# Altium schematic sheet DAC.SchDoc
size A3
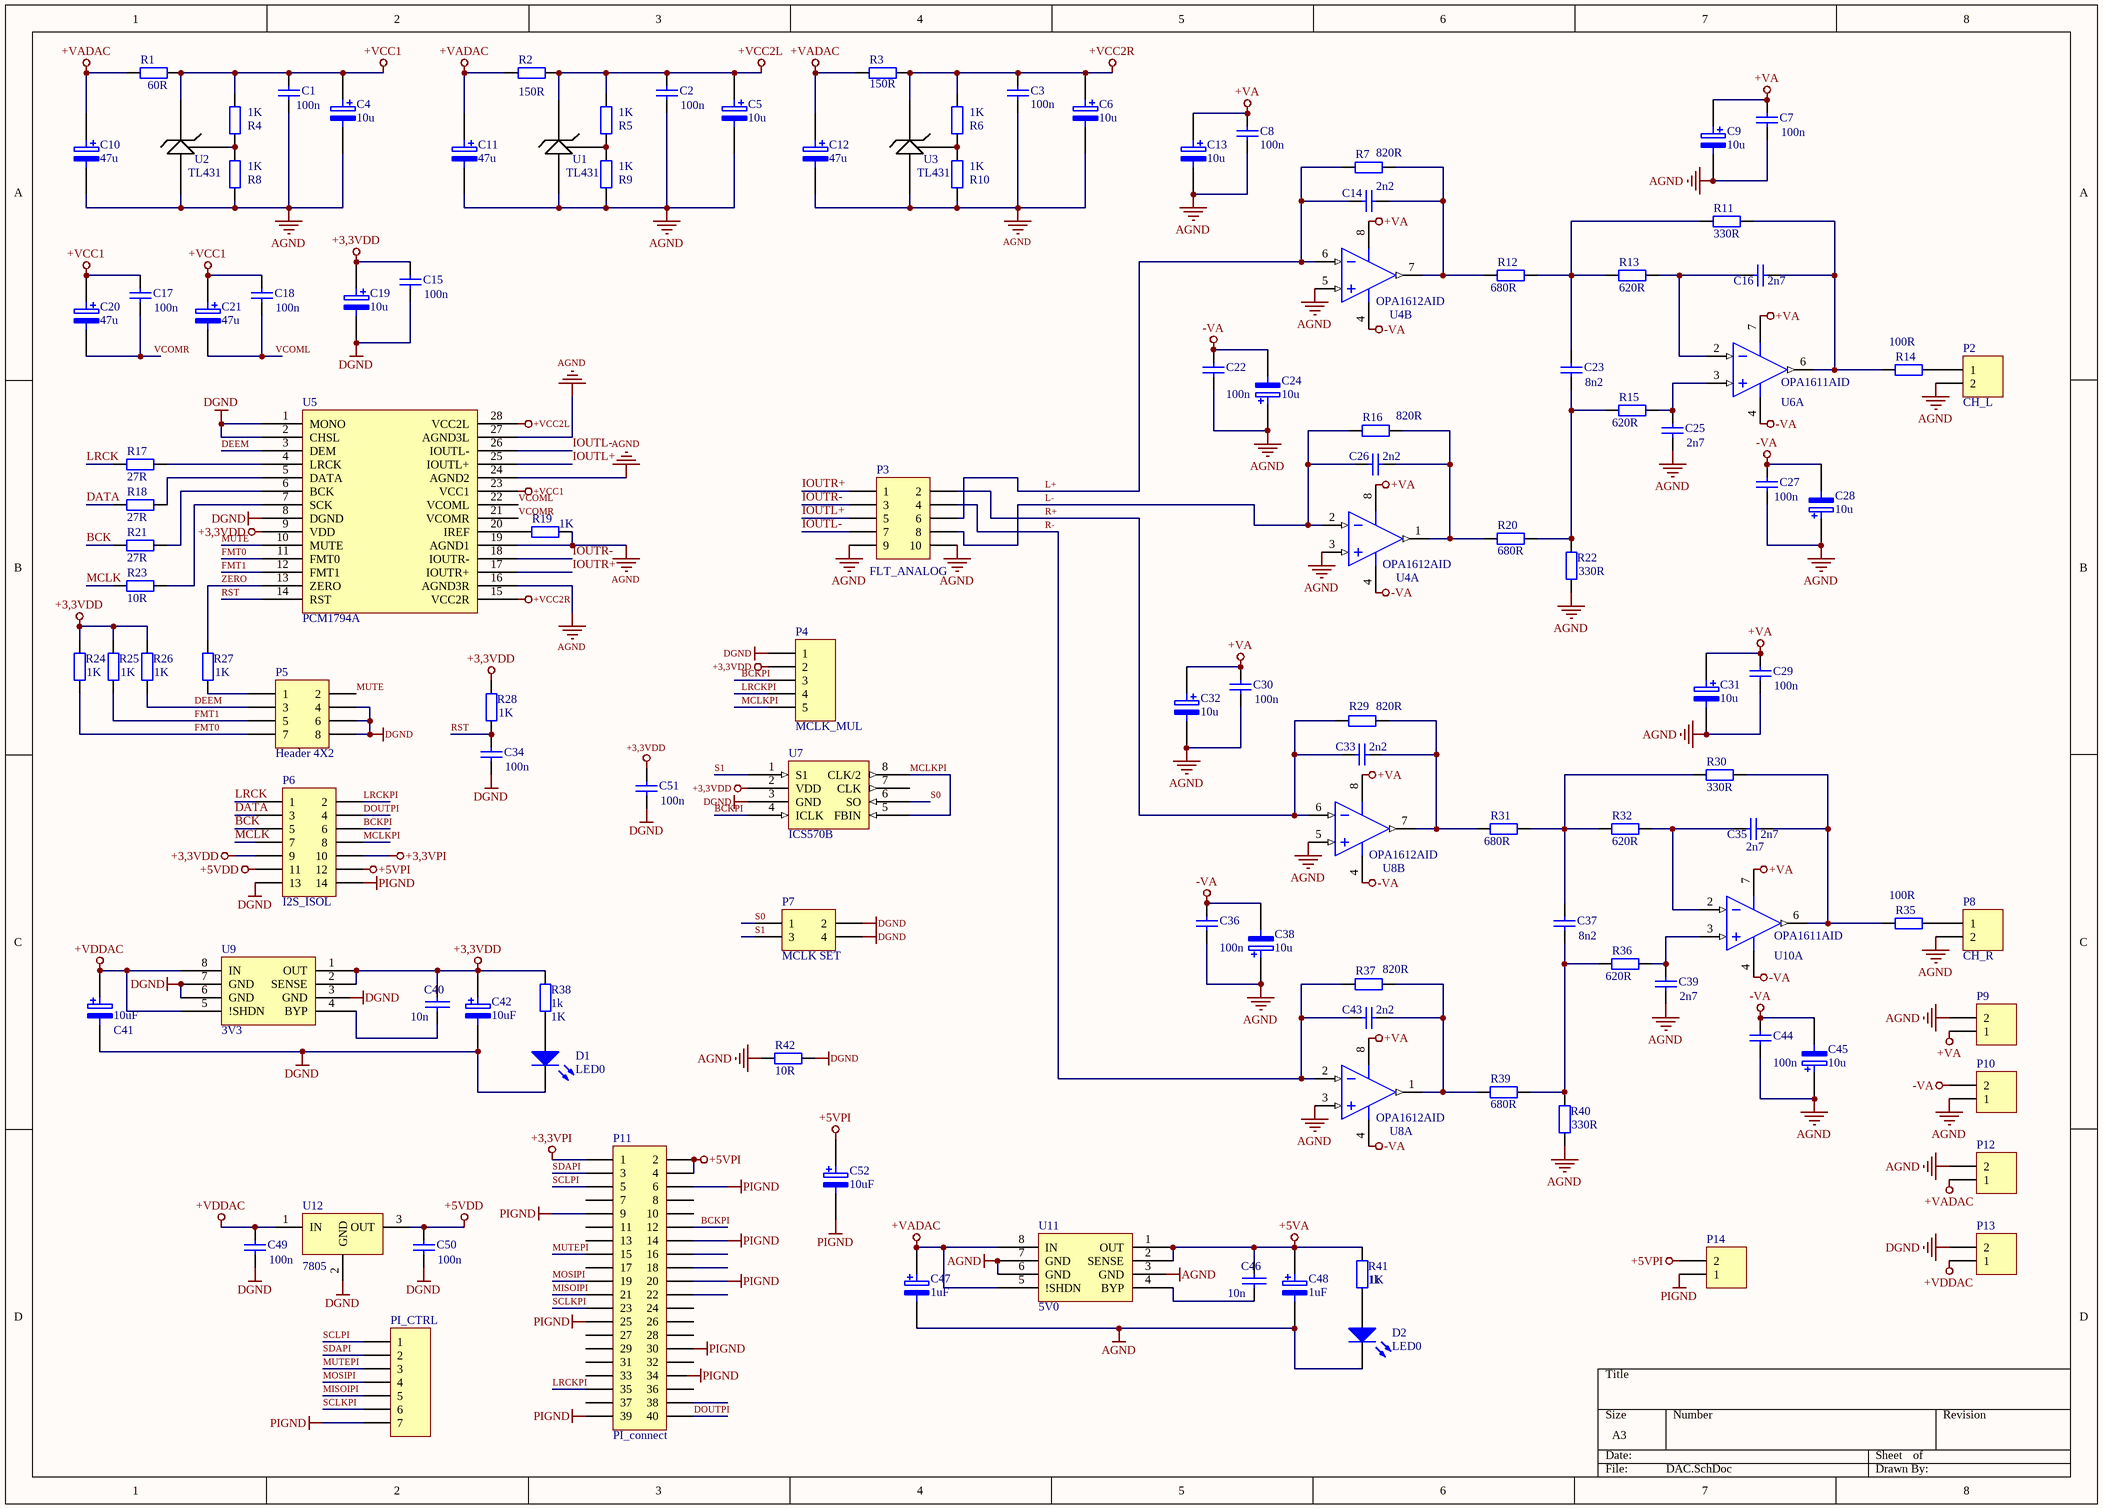
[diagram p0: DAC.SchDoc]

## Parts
C1  value 100n  [1206]
C2  100n  [1206]
C3  100n  [1206]
C4  10u  [10uf/25v]
C5  10u  [10uf/25v]
C6  10u  [10uf/25v]
C7  100n  [1206]
C8  100n  [1206]
C9  10u  [10uf/25v]
C10  47u  [47u/25v]
C11  47u  [47u/25v]
C12  47u  [47u/25v]
C13  10u  [10uf/25v]
C14  2n2  [RAD0.2]
C15  value 100n  [1206]
C16  2n7  [RAD0.2]
C17  value 100n  [1206]
C18  value 100n  [1206]
C19  value 10u  [10uf/25v]
C20  47u  [47u/25v]
C21  47u  [47u/25v]
C22  100n  [1206]
C23  8n2  [RAD0.2]
C24  10u  [10uf/25v]
C25  2n7  [RAD0.2]
C26  2n2  [RAD0.2]
C27  100n  [1206]
C28  10u  [10uf/25v]
C29  100n  [1206]
C30  100n  [1206]
C31  10u  [10uf/25v]
C32  10u  [10uf/25v]
C33  2n2  [RAD0.2]
C34  100n  [1206]
C35  2n7  [RAD0.2]
C36  100n  [1206]
C37  8n2  [RAD0.2]
C38  10u  [10uf/25v]
C39  2n7  [RAD0.2]
C40  10n  [1206]
C41  10uF  [10uSMD]
C42  10uF  [3528]
C43  2n2  [RAD0.2]
C44  100n  [1206]
C45  10u  [10uf/25v]
C46  10n  [1206]
C47  1uF  [10uSMD]
C48  1uF  [3528]
C49  value 100n  [1206]
C50  value 100n  [1206]
C51  100n  [1206]
C52  10uF  [3528]
D1  LED0  [1206]
D2  LED0  [1206]
P2  CH_L  [HDR1X2]
P3  FLT_ANALOG  [HDR2X5]
P4  MCLK_MUL  [HDR1X5]
P5  Header 4X2  [HDR2X4]
P6  I2S_ISOL  [HDR2X7]
P7  MCLK SET  [HDR2X2]
P8  CH_R  [HDR1X2]
P9  (no value)  [wago]
P10  (no value)  [wago]
P11  PI_connect  [HDR2X20]
P12  (no value)  [wago]
P13  (no value)  [wago]
P14  (no value)  [wago]
PI_CTRL  (no value)  [HDR1X7]
R1  60R  [1206]
R2  150R  [1206]
R3  150R  [1206]
R4  1k  [1206]
R5  1k  [1206]
R6  1k  [1206]
R7  820R  [1206]
R8  1k  [1206]
R9  1k  [1206]
R10  1k  [1206]
R11  330R  [1206]
R12  680R  [1206]
R13  620R  [1206]
R14  100R  [1206]
R15  620R  [1206]
R16  820R  [1206]
R17  27R  [1206]
R18  27R  [1206]
R19  1k  [1206]
R20  680R  [1206]
R21  27R  [1206]
R22  330R  [1206]
R23  value 10R  [1206]  (hidden comment: 27R)
R24  1k  [1206]
R25  1k  [1206]
R26  1k  [1206]
R27  1k  [1206]
R28  1k  [1206]
R29  820R  [1206]
R30  330R  [1206]
R31  680R  [1206]
R32  620R  [1206]
R35  100R  [1206]
R36  620R  [1206]
R37  820R  [1206]
R38  1k  [1206]
R39  680R  [1206]
R40  330R  [1206]
R41  1k  [1206]
R42  10R  [1206]
U1  TL431  [sot23-3]
U2  TL431  [sot23-3]
U3  TL431  [sot23-3]
U4  OPA1612AID  [TI-D8_N]  (parts A,B of 2)
U5  PCM1794A  [pcm1796]
U6  OPA1611AID  [TI-D8_N]  (part A of 2)
U7  ICS570B  [TI-D8_n]
U8  OPA1612AID  [TI-D8_N]  (parts A,B of 2)
U9  3V3  [TI-D8_N]
U10  OPA1611AID  [TI-D8_N]  (part A of 2)
U11  5V0  [TI-D8_n]
U12  7805  [78XXST]

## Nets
+3,3VDD: C15.1 C19.1 C40.1 C42.1 C51.1 P4.2 P6.9 R24.1 R25.1 R26.1 R28.1 R38.1 U5.9(VDD) U7.2(VDD) U9.1(OUT) U9.2(SENSE)
+3,3VPI: P6.10 P11.1
+5VA: C46.1 C48.1 R41.1 U11.1(OUT) U11.2(SENSE)
+5VDD: C50.1 P6.11 U12.3(OUT)
+5VPI: C52.1 P6.12 P11.2 P11.4 P14.2
+VA: C7.1 C8.1 C9.1 C13.1 C29.1 C30.1 C31.1 C32.1 P9.1 U4.8(V+) U6.7(V+) U8.8(V+) U10.7(V+)
+VADAC: C10.1 C11.1 C12.1 C47.1 P12.1 R1.1 R2.1 R3.1 U11.5(!SHDN) U11.8(IN)
+VCC1: C1.1 C4.1 C17.1 C18.1 C20.1 C21.1 R1.2 R4.1 U2.1(K) U5.23(VCC1)
+VCC2L: C2.1 C5.1 R2.2 R5.1 U1.1(K) U5.28(VCC2L)
+VCC2R: C3.1 C6.1 R3.2 R6.1 U3.1(K) U5.15(VCC2R)
+VDDAC: C41.1 C49.1 P13.1 U9.5(!SHDN) U9.8(IN) U12.1(IN)
-VA: C22.1 C24.2 C27.1 C28.2 C36.1 C38.2 C44.1 C45.2 P10.2 U4.4(V-) U6.4(V-) U8.4(V-) U10.4(V-)
AGND: C1.2 C2.2 C3.2 C4.2 C5.2 C6.2 C7.2 C8.2 C9.2 C10.2 C11.2 C12.2 C13.2 C22.2 C24.1 C25.2 C27.2 C28.1 C29.2 C30.2 C31.2 C32.2 C36.2 C38.1 C39.2 C44.2 C45.1 C47.2 C48.2 D2.2(K) P2.2 P3.9 P3.10 P8.2 P9.2 P10.1 P12.2 R8.2 R9.2 R10.2 R19.1 R22.1 R40.1 R42.1 U1.3(A) U2.3(A) U3.3(A) U4.3(IN_A+) U4.5(IN_B+) U5.16(AGND3R) U5.19(AGND1) U5.24(AGND2) U5.27(AGND3L) U8.3(IN_A+) U8.5(IN_B+) U11.6(GND) U11.7(GND)
DGND: C15.2 C19.2 C34.2 C41.2 C42.2 C49.2 C50.2 C51.2 D1.2(K) P4.1 P5.4 P5.6 P5.8 P6.13 P7.2 P7.4 P13.2 R42.2 U5.1(MONO) U5.2(CHSL) U5.8(DGND) U7.3(GND) U9.6(GND) U9.7(GND) U12.2(GND)
PIGND: C52.2 P6.14 P11.6 P11.9 P11.14 P11.20 P11.25 P11.30 P11.39 P14.1 PI_CTRL.7
BCK: P6.5 R21.1
BCKPI: P4.3 P6.6 P11.12 U7.4(ICLK)
DATA: P6.3 R18.1
DEEM: P5.3 R26.2 U5.3(DEM)
DOUTPI: P6.4 P11.40
FMT0: P5.7 R24.2 U5.11(FMT0)
FMT1: P5.5 R25.2 U5.12(FMT1)
IOUTL+: P3.5 U5.25(IOUTL+)
IOUTL-: P3.7 U5.26(IOUTL-)
IOUTR+: P3.1 U5.17(IOUTR+)
IOUTR-: P3.3 U5.18(IOUTR-)
L+: C14.1 P3.6 R7.2 U4.6(IN_B-)
L-: C26.1 P3.8 R16.2 U4.2(IN_A-)
LRCK: P6.1 R17.1
LRCKPI: P4.4 P6.2 P11.35
MCLK: P6.7 R23.1
MCLKPI: P4.5 P6.8 U7.5(FBIN) U7.8(CLK/2)
MISOIPI: P11.21 PI_CTRL.5
MOSIPI: P11.19 PI_CTRL.4
MUTE: P5.2 U5.10(MUTE)
MUTEPI: P11.15 PI_CTRL.3
R+: C33.1 P3.2 R29.2 U8.6(IN_B-)
R-: C43.1 P3.4 R37.2 U8.2(IN_A-)
RST: C34.1 R28.2 U5.14(RST)
S0: P7.1 U7.6(SO)
S1: P7.3 U7.1(S1)
SCLKPI: P11.23 PI_CTRL.6
SCLPI: P11.5 PI_CTRL.1
SDAPI: P11.3 PI_CTRL.2
VCOML: C18.2 C21.2 U5.22(VCOML)
VCOMR: C17.2 C20.2 U5.21(VCOMR)
ZERO: R27.1 U5.13(ZERO)
NetC14_2: C14.2 R7.1 R12.2 U4.7(OUT_B)
NetC16_1: C16.1 R13.1 U6.2(IN-)
NetC16_2: C16.2 R11.1 R14.2 U6.6(OUT)
NetC23_1: C23.1 R11.2 R12.1 R13.2
NetC23_2: C23.2 R15.2 R20.1 R22.2
NetC25_1: C25.1 R15.1 U6.3(IN+)
NetC26_2: C26.2 R16.1 R20.2 U4.1(OUT_A)
NetC33_2: C33.2 R29.1 R31.2 U8.7(OUT_B)
NetC35_1: C35.1 R32.1 U10.2(IN-)
NetC35_2: C35.2 R30.1 R35.2 U10.6(OUT)
NetC37_1: C37.1 R30.2 R31.1 R32.2
NetC37_2: C37.2 R36.2 R39.1 R40.2
NetC39_1: C39.1 R36.1 U10.3(IN+)
NetC40_2: C40.2 U9.4(BYP)
NetC43_2: C43.2 R37.1 R39.2 U8.1(OUT_A)
NetC46_2: C46.2 U11.4(BYP)
NetD1_1: D1.1(A) R38.2
NetD2_1: D2.1(A) R41.2
NetP2_1: P2.1 R14.1
NetP5_1: P5.1 R27.2
NetP8_1: P8.1 R35.1
NetR4_2: R4.2 R8.1 U2.2(REF)
NetR5_2: R5.2 R9.1 U1.2(REF)
NetR6_2: R6.2 R10.1 U3.2(REF)
NetR17_2: R17.2 U5.4(LRCK)
NetR18_2: R18.2 U5.5(DATA)
NetR19_2: R19.2 U5.20(IREF)
NetR21_2: R21.2 U5.6(BCK)
NetR23_2: R23.2 U5.7(SCK)

Not connected (* = marked no-connect by the designer): P11 7 8 10 11 13 16 17 18 22 24 26 27 28 29 31 32 33 34 36 37 38; U7 7(CLK); U9 3(GND); U11 3(GND)

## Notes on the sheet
- Labels drawn without touching a wire or pin: AGND, DGND, PIGND

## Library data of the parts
C1-C3 C7 C8 C14-C18 C22 C23 C25-C27 C29 C30 C33-C37 C39 C43 C44 C49-C51 = Cap: Capacitor
C4-C6 C9-C13 C19-C21 C24 C28 C31 C32 C38 C41 C42 C45 C47 C48 C52 = ELECTRO2: Electrolytic Capacitor
C40 C46 = CAP: Capacitor
D1 D2 = LED0: Typical INFRARED GaAs LED
P2 P8-P10 P12-P14 = Header 2: Header, 2-Pin
P3 = Header 5X2: Header, 5-Pin, Dual row
P4 = Header 5: Header, 5-Pin
P5 = Header 4X2: Header, 4-Pin, Dual row
P6 = Header 7X2: Header, 7-Pin, Dual row
P7 = Header 2X2: Header, 2-Pin, Dual row
P11 = Header 20X2: Header, 20-Pin, Dual row
PI_CTRL = Header 7: Header, 7-Pin
R1-R32 R35-R42 = Res2: Resistor
U4 U8 = OPA1612AID: 1.1 nV/rtHz Noise, Low Power, Precision Operational Amplifier, 4.5 to 36 V, -40 to 85 degC, 8-pin SOIC (D8), Green (RoHS & no Sb/Br); Manufacturer: Texas Instruments; GBW(Typ)(MHz): 40; Iq per channel(Max)(mA): 4.5; Number of Channels: 2; SubFamily: Audio Operational Amplifier; Vmax(V): 36; Vn at Flatband(Typ)(nV/rtHz): 1.1
U6 U10 = OPA1611AID: 1.1 nV/rtHz Noise, Low Power, Precision Operational Amplifier, 4.5 to 36 V, -40 to 85 degC, 8-pin SOIC (D8), Green (RoHS & no Sb/Br); Manufacturer: Texas Instruments; GBW(Typ)(MHz): 40; Iq per channel(Max)(mA): 4.5; Number of Channels: 1; SubFamily: Audio Operational Amplifier; Vmax(V): 36; Vn at Flatband(Typ)(nV/rtHz): 1.1
U7 = ICS570
U9 U11 = LT1763
U12 = 78XX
